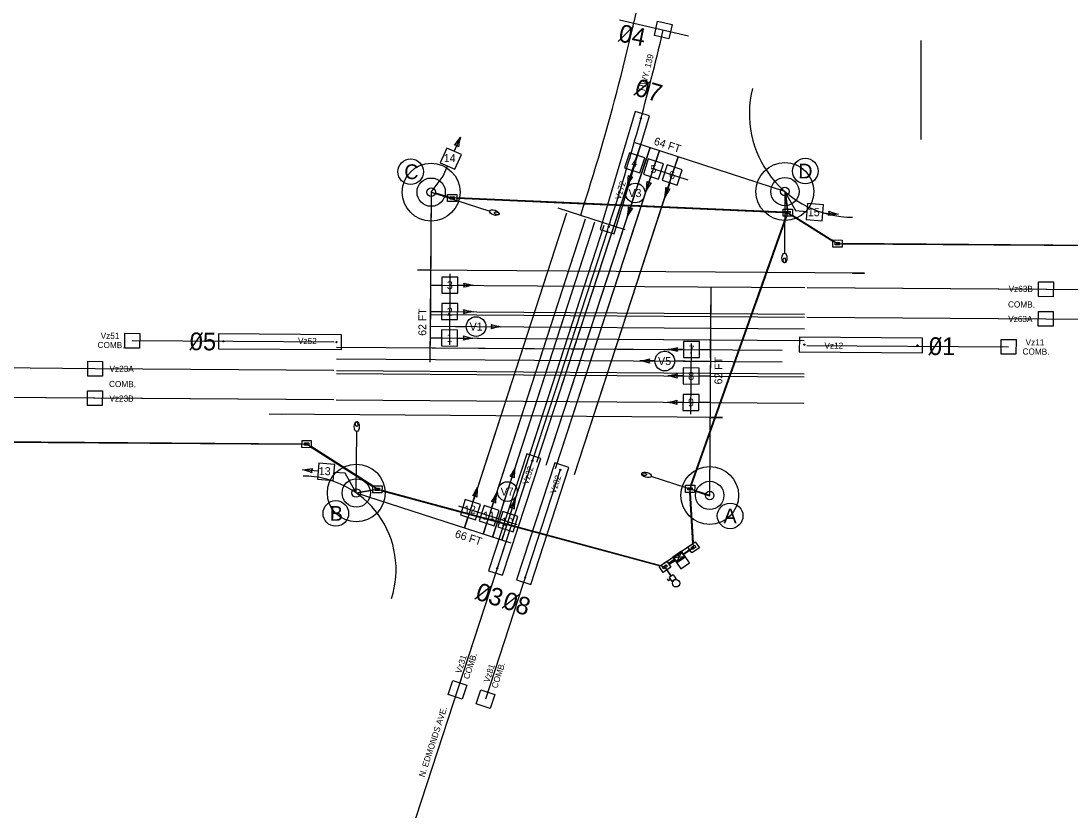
# Model space of a CAD drawing. Extents: x 1802372 to 1804337, y 572813 to 574117.
# Drawn here: x 1803249 to 1803675.5, y 573622.8 to 573943.6 of the extents above; entities that cross this region are included whole.
import ezdxf

# ---------------------------------------------------------------- set-up
doc = ezdxf.new("R2010")
doc.units = 0
for name, color, linetype in [('DSN_DRFT_Common-Annotations', 7, 'Continuous'), ('DSN_DRFT_DNC', 7, 'Continuous'), ('DSN_TRAF_Permanent Signal', 7, 'Continuous'), ('DSN_TRAF_Permanent Signal Notes', 7, 'Continuous'), ('S_PRIMARY_CTL', 7, 'Continuous')]:
    doc.layers.add(name, color=color, linetype=linetype)

msp = doc.modelspace()

# ---------------------------------------------------------------- linework, layer by layer
at = {"layer": 'DSN_DRFT_Common-Annotations'}
for p, q in [((1803497.78, 573941.43), (1803491.61, 573935.25)), ((1803322.49, 573816.96), (1803317.6, 573809.73)), ((1803622.61, 573815.02), (1803617.72, 573807.79)), ((1803451.25, 573710.34), (1803444.4, 573704.94))]:
    msp.add_line(p, q, dxfattribs=at)
at = {"layer": 'DSN_DRFT_DNC'}
for p, q in [((1803492.06, 573944.05), (1803520.05, 573937.6)), ((1803614.51, 573935.66), (1803614.51, 573895.36)), ((1803458.54, 573764.19), (1803500.69, 573893.36)), ((1803462.35, 573762.95), (1803504.49, 573892.12)), ((1803466.15, 573761.71), (1803508.29, 573890.88)), ((1803458.54, 573764.19), (1803499.28, 573889.04)), ((1803462.35, 573762.95), (1803503.08, 573887.8)), ((1803466.15, 573761.71), (1803506.88, 573886.56)), ((1803473.75, 573759.23), (1803515.9, 573888.4)), ((1803473.75, 573759.23), (1803514.49, 573884.08)), ((1803519.94, 573878.82), (1803506.22, 573883.3)), ((1803415.58, 573873.99), (1803415.1, 573804.85)), ((1803415.58, 573873.99), (1803424.12, 573871.62)), ((1803559.27, 573874.24), (1803560.47, 573865.64)), ((1803560.47, 573865.64), (1803424.12, 573871.62)), ((1803470.53, 573865.42), (1803429.13, 573737.47)), ((1803470.53, 573865.42), (1803429.8, 573739.56)), ((1803466.98, 573867.62), (1803494.31, 573858.78)), ((1803520.74, 573753.38), (1803560.47, 573865.64)), ((1803560.47, 573865.64), (1803580.64, 573853.09)), ((1803478.14, 573862.96), (1803436.74, 573735.01)), ((1803478.14, 573862.96), (1803437.41, 573737.1)), ((1803481.95, 573861.73), (1803440.54, 573733.78)), ((1803481.95, 573861.73), (1803441.22, 573735.86)), ((1803485.76, 573860.5), (1803444.35, 573732.55)), ((1803485.76, 573860.5), (1803445.03, 573734.63)), ((1803487.19, 573858.45), (1803248.96, 573128.28)), ((1803580.64, 573853.09), (1804318.42, 573847.97)), ((1803415, 573842.24), (1803410, 573842.28)), ((1803591.63, 573841.02), (1803410.01, 573842.28)), ((1803423.19, 573840.82), (1803422.99, 573811.94)), ((1803586.63, 573841.05), (1803591.63, 573841.02)), ((1803415.31, 573836.24), (1803567.31, 573835.19)), ((1803528.72, 573750.7), (1803529.31, 573835.49)), ((1803529.11, 573806.6), (1803529.31, 573835.49)), ((1803568.31, 573835.18), (1803665.31, 573834.51)), ((1803568.31, 573835.18), (1804318.29, 573829.97)), ((1803665.31, 573834.51), (1803810.31, 573833.5)), ((1803415.23, 573824.24), (1803567.23, 573823.19)), ((1803415.24, 573825.49), (1803567.24, 573824.44)), ((1803568.23, 573823.18), (1803665.23, 573822.51)), ((1803665.23, 573822.51), (1803810.22, 573821.5)), ((1803415.19, 573818.15), (1803415.1, 573804.85)), ((1803415.2, 573819.49), (1803567.19, 573818.44)), ((1803415.2, 573819.49), (1803567.19, 573818.44)), ((1803376.15, 573813.01), (1803294.15, 573813.58)), ((1803415.17, 573814.74), (1803567.16, 573813.69)), ((1803416.11, 573814.74), (1803528.7, 573813.95)), ((1803377.14, 573811.01), (1803558.13, 573809.75)), ((1803416.03, 573810.74), (1803528.72, 573809.95)), ((1803521.11, 573783.75), (1803521.3, 573812.4)), ((1803568.15, 573811.68), (1803650.15, 573811.11)), ((1803377.11, 573806.26), (1803558.1, 573805)), ((1803377.11, 573806.26), (1803558.1, 573805)), ((1803279.08, 573802.22), (1803134.08, 573803.29)), ((1803376.07, 573801.52), (1803279.08, 573802.22)), ((1803377.06, 573800.26), (1803567.1, 573798.94)), ((1803377.07, 573801.51), (1803567.11, 573800.19)), ((1803375.99, 573789.52), (1802626.01, 573794.73)), ((1803278.99, 573790.22), (1803133.99, 573791.29)), ((1803375.99, 573789.52), (1803278.99, 573790.22)), ((1803376.99, 573789.51), (1803567.02, 573788.19)), ((1803354.73, 573783.66), (1803349.73, 573783.7)), ((1803533.95, 573782.42), (1803349.73, 573783.7)), ((1803528.95, 573782.45), (1803533.95, 573782.42)), ((1802625.88, 573776.72), (1803364.98, 573771.59)), ((1803393.73, 573753.2), (1803364.98, 573771.59)), ((1803456.33, 573763.86), (1803426.24, 573671.65)), ((1803468.05, 573761.09), (1803437.65, 573667.92)), ((1803520.74, 573753.38), (1803528.72, 573750.7)), ((1803522.16, 573729.59), (1803520.74, 573753.38)), ((1803385.16, 573751.7), (1803393.73, 573753.2)), ((1803393.73, 573753.2), (1803510.53, 573721.67)), ((1803426.69, 573746.51), (1803450.37, 573738.85)), ((1803510.04, 573723.1), (1803521.01, 573730.57)), ((1803518.1, 573726.9), (1803520.6, 573728.56)), ((1803520.61, 573728.54), (1803522.16, 573729.59)), ((1803512.06, 573722.74), (1803514.52, 573724.46)), ((1803515.52, 573726.84), (1803516.3, 573725.7)), ((1803513.11, 573717.88), (1803510.53, 573721.67))]:
    msp.add_line(p, q, dxfattribs=at)
msp.add_lwpolyline([(1803514.19, 573725.53), (1803517.23, 573727.6), (1803518.4, 573725.88), (1803515.36, 573723.81)], close=True, dxfattribs=at)
for centre, radius in [((1803500.77, 573903.97), 0.25), ((1803415.58, 573873.99), 11.75), ((1803559.27, 573874.24), 11.75), ((1803415.58, 573873.99), 5.75), ((1803559.27, 573874.24), 5.75), ((1803487.66, 573859.88), 0.25), ((1803331.15, 573813.33), 0.25), ((1803377.15, 573813.01), 0.25), ((1803567.15, 573812.01), 0.25), ((1803613.15, 573811.69), 0.25), ((1803385.16, 573751.7), 11.75), ((1803456.64, 573764.81), 0.25), ((1803528.72, 573750.7), 11.75), ((1803468.05, 573761.09), 0.25), ((1803385.16, 573751.7), 5.75), ((1803528.72, 573750.7), 5.75), ((1803442.37, 573721.08), 0.25), ((1803453.78, 573717.36), 0.25)]:
    msp.add_circle(centre, radius, dxfattribs=at)
for centre, radius, start, end in [((1802579.36, 574154.64), 942.69, 342.08093, 348.84522), ((1802579.36, 574154.64), 954.93, 342.08085, 347.00766), ((1803587.08, 573906.05), 42.25, 166.1427, 269.6021), ((1802579.36, 574154.64), 954.93, 341.93028, 342.08085), ((1803363.33, 573720.6), 38, 341.9303, 89.6021)]:
    msp.add_arc(centre, radius, start, end, dxfattribs=at)
at = {"layer": 'DSN_TRAF_Permanent Signal'}
for p, q in [((1803504.65, 573918.99), (1803497.94, 573913.41)), ((1803424.9, 573890.58), (1803427.45, 573896.33)), ((1803559.27, 573874.24), (1803498.43, 573894.1)), ((1803500.69, 573893.36), (1803499.26, 573888.99)), ((1803504.49, 573892.12), (1803501.04, 573881.56)), ((1803508.29, 573890.88), (1803506.86, 573886.51)), ((1803515.9, 573888.4), (1803514.47, 573884.03)), ((1803420.4, 573880.44), (1803422.27, 573884.64)), ((1803497.26, 573882.8), (1803495.31, 573876.82)), ((1803501.04, 573881.56), (1803499.7, 573877.45)), ((1803415.58, 573873.99), (1803420.4, 573880.44)), ((1803504.86, 573880.32), (1803502.91, 573874.34)), ((1803512.47, 573877.84), (1803510.52, 573871.86)), ((1803415.58, 573873.99), (1803415.15, 573811.99)), ((1803415.58, 573873.99), (1803439.36, 573866.3)), ((1803424.09, 573871.5), (1803416.99, 573873.47)), ((1803417.09, 573873.7), (1803424.15, 573871.74)), ((1803422.25, 573872.01), (1803417.23, 573873.41)), ((1803417.29, 573873.65), (1803422.25, 573872.27)), ((1803559.27, 573874.24), (1803559.1, 573849.24)), ((1803559.27, 573874.24), (1803563.65, 573866.52)), ((1803559.53, 573873.31), (1803560.39, 573867.1)), ((1803558.6, 573865.6), (1803425.99, 573871.42)), ((1803558.6, 573865.85), (1803426, 573871.67)), ((1803559, 573865.83), (1803454.07, 573870.44)), ((1803559.06, 573865.58), (1803462.49, 573869.82)), ((1803497.22, 573869.84), (1803495.34, 573864.07)), ((1803559.35, 573872.75), (1803560.2, 573866.67)), ((1803559.39, 573872.5), (1803560.14, 573867.1)), ((1803559.63, 573872.53), (1803560.39, 573867.1)), ((1803521.16, 573754.92), (1803559.91, 573864.44)), ((1803547.33, 573828.13), (1803560.23, 573864.58)), ((1803563.65, 573866.52), (1803568.23, 573866.11)), ((1803574.7, 573865.56), (1803580.97, 573865)), ((1803521.13, 573754.83), (1803559.82, 573864.19)), ((1803521.39, 573754.83), (1803560.09, 573864.19)), ((1803415.31, 573836.24), (1803419.91, 573836.21)), ((1803426.41, 573836.18), (1803432.7, 573836.14)), ((1803415.24, 573825.49), (1803419.84, 573825.46)), ((1803426.34, 573825.43), (1803432.63, 573825.39)), ((1803415.2, 573819.49), (1803425.5, 573819.42)), ((1803425.5, 573819.42), (1803429.83, 573819.39)), ((1803437.83, 573819.34), (1803443.89, 573819.29)), ((1803415.17, 573814.74), (1803419.76, 573814.71)), ((1803426.26, 573814.68), (1803432.55, 573814.64)), ((1803518.04, 573810.01), (1803511.75, 573810.06)), ((1803529.14, 573809.95), (1803524.54, 573809.98)), ((1803528.72, 573750.7), (1803529.15, 573812.7)), ((1803506.47, 573805.36), (1803500.41, 573805.4)), ((1803518.8, 573805.27), (1803514.47, 573805.3)), ((1803529.1, 573805.2), (1803518.8, 573805.27)), ((1803517.96, 573799.26), (1803511.67, 573799.31)), ((1803529.06, 573799.2), (1803524.46, 573799.23)), ((1803517.89, 573788.51), (1803511.6, 573788.56)), ((1803528.99, 573788.45), (1803524.39, 573788.48)), ((1803385.16, 573751.7), (1803385.34, 573776.7)), ((1803369.64, 573760.61), (1803363.37, 573761.15)), ((1803380.7, 573759.69), (1803376.12, 573760.08)), ((1803385.16, 573751.7), (1803380.7, 573759.69)), ((1803447.76, 573756.07), (1803449.63, 573761.84)), ((1803528.72, 573750.7), (1803504.96, 573758.46)), ((1803432.53, 573748.04), (1803434.47, 573754.02)), ((1803385.16, 573751.7), (1803447.96, 573731.38)), ((1803386.86, 573752.12), (1803391.86, 573753)), ((1803391.85, 573752.74), (1803386.9, 573751.88)), ((1803395.6, 573752.56), (1803508.54, 573722.08)), ((1803395.61, 573752.82), (1803508.78, 573722.24)), ((1803440.14, 573745.57), (1803442.08, 573751.56)), ((1803447.75, 573743.11), (1803449.69, 573749.1)), ((1803521.94, 573731.21), (1803520.71, 573751.92)), ((1803522.18, 573731.37), (1803520.96, 573751.92)), ((1803522.61, 573752.62), (1803528.68, 573750.58)), ((1803522.61, 573752.62), (1803527.03, 573751.14)), ((1803522.62, 573752.88), (1803528.76, 573750.82)), ((1803522.62, 573752.88), (1803527.11, 573751.38)), ((1803443.96, 573744.34), (1803445.3, 573748.46)), ((1803429.13, 573737.47), (1803430.54, 573741.85)), ((1803440.54, 573733.78), (1803443.96, 573744.34)), ((1803436.74, 573735.01), (1803438.15, 573739.38)), ((1803444.35, 573732.55), (1803445.77, 573736.92)), ((1803518.03, 573727), (1803520.53, 573728.66)), ((1803518.17, 573726.8), (1803520.67, 573728.45)), ((1803511.88, 573723.02), (1803514.33, 573724.73)), ((1803512.02, 573722.81), (1803514.48, 573724.53)), ((1803512.11, 573722.68), (1803514.57, 573724.4)), ((1803512.18, 573722.57), (1803514.64, 573724.29)), ((1803514.21, 573725.54), (1803518.4, 573725.88)), ((1803515.28, 573723.35), (1803518.86, 573725.79)), ((1803517.23, 573727.6), (1803515.36, 573723.81)), ((1803513.18, 573717.93), (1803511.18, 573720.86)), ((1803511.28, 573720.42), (1803512.89, 573718.06)), ((1803511.28, 573720.42), (1803513.04, 573717.84)), ((1803513.18, 573717.93), (1803511.42, 573720.51)), ((1803511.45, 573716.76), (1803512.02, 573715.93)), ((1803512.84, 573716.49), (1803512.02, 573715.93)), ((1803513.93, 573718.45), (1803512.28, 573717.32)), ((1803512.28, 573717.32), (1803513.41, 573715.67)), ((1803515.06, 573716.79), (1803513.41, 573715.67)), ((1803513.93, 573718.45), (1803515.06, 573716.79)), ((1803440.17, 573713.96), (1803433.31, 573708.56))]:
    msp.add_line(p, q, dxfattribs=at)
for points in [[(1803506.24, 573937.7), (1803507.59, 573943.55), (1803513.44, 573942.2), (1803512.09, 573936.36)], [(1803498.47, 573906.75), (1803484.21, 573858.82), (1803489.96, 573857.11), (1803504.22, 573905.03)], [(1803427.87, 573889.26), (1803421.93, 573891.9), (1803419.28, 573885.97), (1803425.22, 573883.32)], [(1803494.17, 573883.81), (1803500.35, 573881.8), (1803502.36, 573887.98), (1803496.18, 573889.99)], [(1803501.77, 573881.33), (1803507.95, 573879.31), (1803509.97, 573885.49), (1803503.79, 573887.51)], [(1803509.38, 573878.85), (1803515.56, 573876.83), (1803517.57, 573883.01), (1803511.4, 573885.03)], [(1803422.26, 573873.1), (1803426.01, 573873.07), (1803425.99, 573870.15), (1803422.24, 573870.18)], [(1803423.25, 573872.09), (1803425, 573872.08), (1803424.99, 573871.16), (1803423.24, 573871.17)], [(1803574.42, 573862.32), (1803574.99, 573868.79), (1803568.52, 573869.37), (1803567.94, 573862.89)], [(1803558.61, 573867.11), (1803562.36, 573867.09), (1803562.34, 573864.17), (1803558.59, 573864.2)], [(1803559.6, 573866.11), (1803561.35, 573866.1), (1803561.34, 573865.18), (1803559.59, 573865.19)], [(1803578.77, 573854.57), (1803582.52, 573854.54), (1803582.5, 573851.62), (1803578.75, 573851.65)], [(1803579.76, 573853.56), (1803581.51, 573853.55), (1803581.51, 573852.63), (1803579.76, 573852.64)], [(1803426.39, 573832.93), (1803426.43, 573839.43), (1803419.93, 573839.48), (1803419.89, 573832.98)], [(1803662.29, 573831.53), (1803662.33, 573837.53), (1803668.33, 573837.49), (1803668.29, 573831.49)], [(1803426.31, 573822.18), (1803426.36, 573828.68), (1803419.86, 573828.73), (1803419.81, 573822.23)], [(1803662.2, 573819.53), (1803662.25, 573825.53), (1803668.25, 573825.49), (1803668.2, 573819.49)], [(1803426.24, 573811.43), (1803426.28, 573817.93), (1803419.79, 573817.98), (1803419.74, 573811.48)], [(1803291.13, 573810.6), (1803291.18, 573816.6), (1803297.18, 573816.56), (1803297.13, 573810.56)], [(1803379.17, 573815.99), (1803329.17, 573816.34), (1803329.13, 573810.34), (1803379.13, 573809.99)], [(1803518.06, 573813.26), (1803518.02, 573806.76), (1803524.52, 573806.72), (1803524.56, 573813.22)], [(1803615.17, 573814.68), (1803565.17, 573815.02), (1803565.13, 573809.02), (1803615.13, 573808.68)], [(1803647.13, 573808.13), (1803647.17, 573814.13), (1803653.17, 573814.09), (1803653.13, 573808.09)], [(1803276.06, 573799.24), (1803276.1, 573805.24), (1803282.1, 573805.2), (1803282.06, 573799.2)], [(1803517.99, 573802.51), (1803517.94, 573796.01), (1803524.44, 573795.97), (1803524.49, 573802.47)], [(1803275.97, 573787.24), (1803276.01, 573793.24), (1803282.01, 573793.2), (1803281.97, 573787.2)], [(1803517.91, 573791.76), (1803517.87, 573785.26), (1803524.37, 573785.22), (1803524.41, 573791.72)], [(1803366.85, 573770.12), (1803363.1, 573770.15), (1803363.12, 573773.06), (1803366.87, 573773.04)], [(1803365.85, 573771.13), (1803364.1, 573771.14), (1803364.11, 573772.06), (1803365.86, 573772.04)], [(1803454.41, 573767.65), (1803438.9, 573720.11), (1803444.61, 573718.25), (1803460.11, 573765.78)], [(1803369.91, 573763.85), (1803369.36, 573757.38), (1803375.84, 573756.83), (1803376.39, 573763.3)], [(1803465.82, 573763.92), (1803450.31, 573716.39), (1803456.01, 573714.53), (1803471.52, 573762.06)], [(1803391.87, 573754.67), (1803395.62, 573754.64), (1803395.6, 573751.73), (1803391.85, 573751.75)], [(1803392.86, 573753.66), (1803394.61, 573753.65), (1803394.61, 573752.73), (1803392.86, 573752.75)], [(1803518.88, 573754.85), (1803522.63, 573754.82), (1803522.61, 573751.91), (1803518.86, 573751.93)], [(1803519.87, 573753.84), (1803521.62, 573753.83), (1803521.62, 573752.91), (1803519.87, 573752.93)], [(1803435.62, 573747.04), (1803429.44, 573749.04), (1803427.44, 573742.85), (1803433.62, 573740.85)], [(1803443.23, 573744.57), (1803437.05, 573746.57), (1803435.05, 573740.39), (1803441.23, 573738.39)], [(1803450.84, 573742.11), (1803444.66, 573744.11), (1803442.66, 573737.93), (1803448.84, 573735.93)], [(1803513.74, 573725.62), (1803516.97, 573720.87), (1803520.55, 573723.31), (1803517.31, 573728.05)], [(1803519.79, 573729.74), (1803522.89, 573731.85), (1803524.53, 573729.44), (1803521.44, 573727.33)], [(1803521.18, 573729.48), (1803522.63, 573730.46), (1803523.15, 573729.71), (1803521.7, 573728.72)], [(1803508.16, 573721.82), (1803511.26, 573723.93), (1803512.9, 573721.52), (1803509.8, 573719.41)], [(1803509.55, 573721.55), (1803510.99, 573722.54), (1803511.51, 573721.78), (1803510.06, 573720.8)], [(1803428.17, 573667.86), (1803422.46, 573669.73), (1803424.32, 573675.43), (1803430.03, 573673.57)], [(1803439.57, 573664.14), (1803433.87, 573666), (1803435.73, 573671.71), (1803441.44, 573669.85)]]:
    msp.add_lwpolyline(points, close=True, dxfattribs=at)
for centre, radius in [((1803407.27, 573882.3), 5.2), ((1803567.58, 573882.55), 5.2), ((1803498.46, 573873.64), 4), ((1803415.58, 573873.99), 1.75), ((1803559.27, 573874.24), 1.75), ((1803433.83, 573819.36), 4), ((1803510.47, 573805.33), 4), ((1803385.16, 573751.7), 1.75), ((1803446.53, 573752.27), 4), ((1803528.72, 573750.7), 1.75), ((1803376.85, 573743.39), 5.2), ((1803537.03, 573742.39), 5.2), ((1803515.08, 573714.99), 1.5)]:
    msp.add_circle(centre, radius, dxfattribs=at)
for centre, radius, start, end in [((1803402.63, 573912.21), 29.47, 319.6614, 327.3995), ((1803455.87, 573888.51), 29.47, 164.6161, 172.3543), ((1803425.31, 573891.52), 1.63, 34.1605, 97.8552), ((1803466.23, 573881.67), 29.47, 350.5386, 358.2767), ((1803521.64, 573863.59), 29.47, 145.5838, 153.322), ((1803496.94, 573881.83), 1.63, 220.083, 283.7776), ((1803473.84, 573879.19), 29.47, 350.5386, 358.2767), ((1803529.25, 573861.11), 29.47, 145.5838, 153.322), ((1803504.55, 573879.35), 1.63, 220.083, 283.7776), ((1803481.45, 573876.71), 29.47, 350.5386, 358.2767), ((1803536.85, 573858.63), 29.47, 145.5838, 153.322), ((1803512.15, 573876.87), 1.63, 220.083, 283.7776), ((1803466.27, 573868.92), 29.47, 350.5386, 358.2767), ((1803521.67, 573850.84), 29.47, 145.5838, 153.322), ((1803496.97, 573869.08), 1.63, 220.083, 283.7776), ((1803575.72, 573865.47), 1.63, 323.1032, 26.7978), ((1803582.8, 573835.59), 29.47, 93.5588, 101.2969), ((1803587.93, 573893.64), 29.47, 248.6041, 256.3422), ((1803427.44, 573836.17), 1.63, 327.7548, 31.4494), ((1803436.91, 573806.97), 29.47, 98.2104, 105.9485), ((1803437.32, 573865.25), 29.47, 253.2557, 260.9938), ((1803427.36, 573825.42), 1.63, 327.7548, 31.4494), ((1803437.24, 573854.5), 29.47, 253.2557, 260.9938), ((1803436.84, 573796.22), 29.47, 98.2104, 105.9485), ((1803438.63, 573819.33), 1.63, 327.7548, 31.4494), ((1803448.1, 573790.12), 29.47, 98.2104, 105.9485), ((1803448.51, 573848.4), 29.47, 253.2557, 260.9938), ((1803427.29, 573814.67), 1.63, 327.7548, 31.4494), ((1803436.76, 573785.47), 29.47, 98.2104, 105.9485), ((1803437.17, 573843.75), 29.47, 253.2557, 260.9938), ((1803507.54, 573839.23), 29.47, 278.2104, 285.9485), ((1803507.13, 573780.95), 29.47, 73.2557, 80.9938), ((1803517.01, 573810.02), 1.63, 147.7548, 211.4494), ((1803496.2, 573834.57), 29.47, 278.2104, 285.9485), ((1803495.79, 573776.29), 29.47, 73.2557, 80.9938), ((1803505.67, 573805.37), 1.63, 147.7548, 211.4494), ((1803507.46, 573828.48), 29.47, 278.2104, 285.9485), ((1803507.06, 573770.2), 29.47, 73.2557, 80.9938), ((1803516.94, 573799.27), 1.63, 147.7548, 211.4494), ((1803507.39, 573817.73), 29.47, 278.2104, 285.9485), ((1803506.98, 573759.45), 29.47, 73.2557, 80.9938), ((1803516.87, 573788.52), 1.63, 147.7548, 211.4494), ((1803361.44, 573790.56), 29.47, 273.7597, 281.4978), ((1803356.51, 573732.48), 29.47, 68.8049, 76.5431), ((1803368.62, 573760.7), 1.63, 143.3041, 206.9987), ((1803423.26, 573775.01), 29.47, 325.722, 333.4601), ((1803448.01, 573756.83), 1.63, 40.2211, 103.9157), ((1803478.71, 573757.07), 29.47, 170.6767, 178.4148), ((1803408.1, 573767.19), 29.47, 325.722, 333.4601), ((1803463.55, 573749.25), 29.47, 170.6767, 178.4148), ((1803432.84, 573749.01), 1.63, 40.2211, 103.9157), ((1803415.71, 573764.73), 29.47, 325.722, 333.4601), ((1803471.16, 573746.78), 29.47, 170.6767, 178.4148), ((1803423.32, 573762.26), 29.47, 325.722, 333.4601), ((1803478.77, 573744.32), 29.47, 170.6767, 178.4148), ((1803440.46, 573746.55), 1.63, 40.2211, 103.9157), ((1803448.07, 573744.08), 1.63, 40.2211, 103.9157)]:
    msp.add_arc(centre, radius, start, end, dxfattribs=at)
for centre, major_axis in [((1803441.27, 573865.68), (1.9, -0.62)), ((1803442.22, 573865.37), (-0.951, 0.308)), ((1803559.08, 573847.24), (-0.01, -2)), ((1803559.08, 573846.24), (0.007, 1)), ((1803385.35, 573778.7), (0.01, 2)), ((1803385.36, 573779.7), (-0.007, -1)), ((1803503.06, 573759.08), (-1.9, 0.62)), ((1803502.1, 573759.39), (0.951, -0.31))]:
    msp.add_ellipse(centre, major_axis=major_axis, ratio=0.5, dxfattribs=at)
at = {"layer": 'S_PRIMARY_CTL'}
for p, q in [((1803562.34, 573864.63), (1803578.77, 573854.4)), ((1803562.34, 573864.34), (1803578.77, 573854.11)), ((1803582.51, 573853.21), (1804316.54, 573848.11)), ((1803582.51, 573852.96), (1804316.54, 573847.86)), ((1802627.75, 573776.59), (1803363.11, 573771.48)), ((1802627.76, 573776.84), (1803363.11, 573771.73)), ((1803391.87, 573754.54), (1803366.85, 573770.54)), ((1803391.87, 573754.24), (1803366.85, 573770.25))]:
    msp.add_line(p, q, dxfattribs=at)

# ---------------------------------------------------------------- texts
at = {"layer": 'DSN_DRFT_Common-Annotations'}
for s, height, rotation, p in [('04', 7.2, 348.7285, (1803491.37, 573935.31)), ('Vz72', 2.5, 73.4344, (1803492.55, 573870.69)), ('Vz63B', 2.5, 359.6021, (1803650.16, 573833.48)), ('COMB.', 2.5, 359.6021, (1803649.89, 573827.13)), ('Vz63A', 2.5, 359.6021, (1803649.97, 573821.23)), ('COMB.', 2.5, 359.6021, (1803280.05, 573810.63)), ('Vz51', 2.5, 359.6021, (1803281.32, 573814.38)), ('05', 7.2, 359.6021, (1803317.48, 573809.74)), ('Vz52', 2.5, 359.6021, (1803361.48, 573812.29)), ('01', 7.2, 359.6021, (1803617.76, 573807.8)), ('Vz11', 2.5, 359.6021, (1803657.06, 573811.72)), ('Vz12', 2.5, 359.6021, (1803575.33, 573810.38)), ('COMB.', 2.5, 359.6021, (1803655.79, 573807.98)), ('Vz23A', 2.5, 359.6021, (1803284.91, 573800.95)), ('COMB.', 2.5, 359.6021, (1803284.71, 573794.77)), ('Vz23B', 2.5, 359.6021, (1803284.86, 573788.89)), ('Vz32', 2.5, 71.948, (1803454.91, 573754.84)), ('Vz82', 2.5, 71.948, (1803466.12, 573751.18)), ('08', 7.2, 341.9303, (1803444.21, 573705.01)), ('Vz31', 2.5, 71.948, (1803427.75, 573678.14)), ('COMB.', 2.5, 71.948, (1803430.93, 573675.8)), ('Vz81', 2.5, 71.948, (1803439.18, 573674.41)), ('COMB.', 2.5, 71.948, (1803442.36, 573672.07))]:
    msp.add_text(s, height=height, rotation=rotation, dxfattribs=at).set_placement(p)
at = {"layer": 'DSN_TRAF_Permanent Signal'}
for s, height, rotation, p in [('07', 7.2, 343.4344, (1803497.82, 573913.45)), ('64 FT', 3.2, 341.9303, (1803505.78, 573893.38)), ('14', 3.25, 359.4423, (1803420.67, 573886.24)), ('4', 3.25, 359.6021, (1803496.98, 573884.28)), ('D', 6, 359.6021, (1803564.68, 573879.57)), ('C', 6, 359.4423, (1803404.65, 573879.33)), ('5', 3.25, 359.6021, (1803504.66, 573881.8)), ('6', 3.25, 359.6021, (1803512.21, 573879.32)), ('V3', 3.25, 359.6021, (1803495.69, 573872.04)), ('15', 3.25, 359.6021, (1803568.57, 573864.23)), ('3', 3.25, 359.6021, (1803421.95, 573834.57)), ('62 FT', 3.2, 89.6021, (1803413.57, 573815.59)), ('2', 3.25, 359.6021, (1803421.92, 573823.82)), ('V1', 3.25, 359.6021, (1803431.17, 573817.76)), ('1', 3.25, 359.6021, (1803421.9, 573813.07)), ('7', 3.25, 359.6021, (1803520.08, 573808.39)), ('V5', 3.25, 359.6021, (1803507.72, 573803.73)), ('62 FT', 3.2, 89.6021, (1803533.84, 573795.83)), ('8', 3.25, 359.6021, (1803519.97, 573797.64)), ('9', 3.25, 359.6021, (1803519.9, 573786.89)), ('13', 3.25, 359.6021, (1803369.91, 573758.96)), ('V7', 3.25, 359.6021, (1803443.77, 573750.66)), ('B', 6, 359.6021, (1803374.36, 573740.41)), ('12', 3.25, 359.6021, (1803428.93, 573743.33)), ('A', 6, 359.6021, (1803534.33, 573739.41)), ('11', 3.25, 359.6021, (1803436.6, 573740.87)), ('10', 3.25, 359.6021, (1803444.08, 573738.41)), ('66 FT', 3.2, 342.0684, (1803424.97, 573733.77)), ('03', 7.2, 341.9303, (1803433.17, 573708.61))]:
    msp.add_text(s, height=height, rotation=rotation, dxfattribs=at).set_placement(p)
at = {"layer": 'DSN_TRAF_Permanent Signal Notes'}
for s, rotation, p in [('HWY. 139', 76.1735, (1803502.35, 573914.96)), ('N. EDMONDS AVE.', 71.9303, (1803412.87, 573635.98))]:
    msp.add_text(s, height=2.5, rotation=rotation, dxfattribs=at).set_placement(p)

doc.saveas('drawing.dxf')
